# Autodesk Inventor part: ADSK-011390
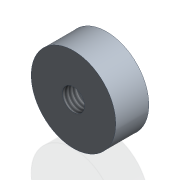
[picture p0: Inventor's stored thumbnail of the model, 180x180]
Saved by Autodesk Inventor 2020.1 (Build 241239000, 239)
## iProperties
Created: 2000-01
Part Number: ADSK-011390
Material: Pearson Aluminium
Document SubType Name: Modeling
Designer: sspink
Density: 2.71 g/cm^3
Appearance: Pearson-Aluminum
Mass: 25.3773 g
Surface Area: 30.8385 cm^2
Volume: 9.36433 cm^3
Control State: 0
Master: False
Checked Out: False
Shininess: 35.0
Length Units: 11269
Angle Units: 11279
Time Units: 11290
Mass Units: 11283
Length Display Precision: 3
Angle Display Precision: 2
Compacted: True
Cutlength: 0.56
Material Desc: ROUND,ALUM,1.2500 DIA
Material_number: A084028
Dimensions: 32x32x12,5 mm
Mass: 0,025 kg
DocNumber: ADSK-011390.ipt
Folder: 01 - Themengebiete\Simplification\01 - Packaging machine\
VDS_Category: 3D Komponenten
Density: 2.71
Volumn: 9.111005688144044
Area: 30.89710672109442
PropertySet Name: Model Information
Author: sspink
Revision Number: -
Title: Distance
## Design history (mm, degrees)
node "Solide1"
  node "Extrusion1" dims "d2" = 12.5, "d3" = 0
  node "Hole1" dims "d6" = 8.376, "d7" = 9.525, "d8" = 6.35, "d9" = 60 deg, "d10" = 27.3, "d11" = 118 deg, "d13" = 20
sketch "Sketch1"
  geometry: C1 r 16 at (0, 0); 1 further point
  constraints: 1 centre point, 1 coincident
  dimensions: "d12" = 32 diameter of C1
node "Corps solides"
node "Corps surfaciques"
sketch "Sketch2"
  geometry: C1 r 16 at (0, 0) reference; 1 further point
  constraints: 1 coincident
